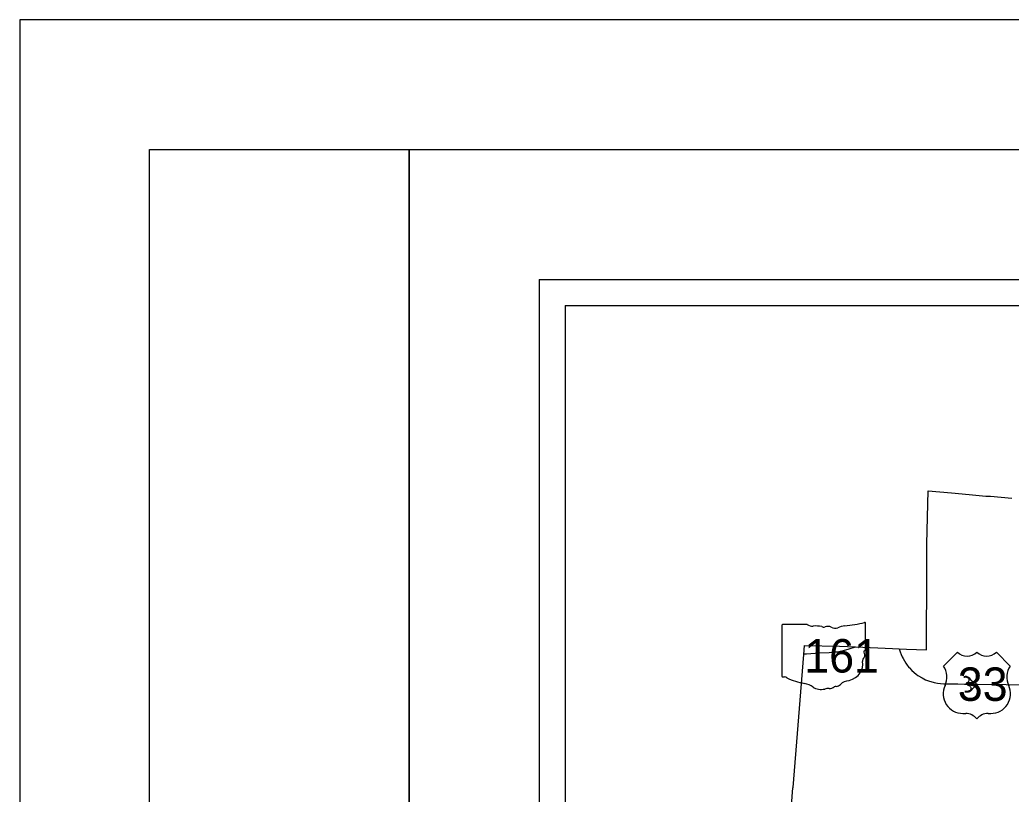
# Model space of a CAD drawing. Extents: x -7.1 to 34, y 0 to 22.
# Drawn here: x 0 to 3.818, y 19.017 to 22 of the extents above; entities that cross this region are included whole.
import ezdxf

# ---------------------------------------------------------------- set-up
doc = ezdxf.new("R2010")
doc.units = 0
for name, color, linetype in [('GM_X_County', 7, 'Continuous'), ('GM_X_Interchange_Ramps', 7, 'Continuous'), ('GM_X_State_Route', 7, 'Continuous'), ('GM_X_State_Shield', 7, 'Continuous'), ('GM_X_US_Route', 7, 'Continuous'), ('GM_X_US_Shield', 7, 'Continuous'), ('SH_Border', 7, 'Continuous'), ('SH_Cut_Line', 7, 'Continuous'), ('SH_Data', 7, 'Continuous')]:
    doc.layers.add(name, color=color, linetype=linetype)

msp = doc.modelspace()

# ---------------------------------------------------------------- linework, layer by layer
at = {"layer": 'GM_X_County'}
msp.add_lwpolyline([(2.9721, 18.9726), (2.9776, 19.0414), (2.9777, 19.0424), (3.0191, 19.5546), (3.0219, 19.5892), (3.1568, 19.5864), (3.2189, 19.5849), (3.3608, 19.5777), (3.3865, 19.5769), (3.4145, 19.5759), (3.4535, 19.5747), (3.4923, 19.5733), (3.4923, 19.5757), (3.4931, 19.8797), (3.4929, 19.981), (3.4977, 20.1851), (3.5882, 20.1772), (3.6564, 20.1717), (3.72, 20.1652), (3.7388, 20.1645), (3.8199, 20.1576)], dxfattribs=at)
at = {"layer": 'GM_X_Interchange_Ramps'}
for points in [[(3.6835, 19.4406), (3.6836, 19.4446), (3.6822, 19.4449), (3.6781, 19.4464), (3.6751, 19.4478), (3.6722, 19.4494), (3.6696, 19.4512), (3.6677, 19.4527), (3.6651, 19.4552), (3.6586, 19.4624), (3.6539, 19.4668), (3.6516, 19.468), (3.6486, 19.4691), (3.6463, 19.4696), (3.6438, 19.4698), (3.6413, 19.4695), (3.6375, 19.4693), (3.6359, 19.4691)], [(3.6359, 19.4673), (3.6376, 19.4675), (3.6408, 19.4683), (3.6437, 19.4685), (3.6459, 19.4682), (3.6479, 19.4675), (3.6498, 19.4664), (3.6511, 19.4653), (3.6525, 19.4638), (3.6535, 19.4621), (3.6544, 19.4601), (3.655, 19.4574), (3.6551, 19.4556), (3.6546, 19.453), (3.6536, 19.4506), (3.6519, 19.4482), (3.6501, 19.4466), (3.6478, 19.4454), (3.6445, 19.4446), (3.6447, 19.4409)], [(3.649, 19.4409), (3.649, 19.4374), (3.6525, 19.4367), (3.6544, 19.436), (3.6563, 19.4352), (3.6583, 19.434), (3.6603, 19.4322), (3.6616, 19.4303), (3.6624, 19.4283), (3.663, 19.426), (3.663, 19.4238), (3.6627, 19.4221), (3.6621, 19.4202), (3.6612, 19.4185), (3.6599, 19.4168), (3.6586, 19.4155), (3.6566, 19.4143), (3.6551, 19.4137), (3.6536, 19.4132), (3.6523, 19.413), (3.6499, 19.4128), (3.6419, 19.4125), (3.6401, 19.4125)], [(3.6401, 19.4111), (3.6423, 19.411), (3.6519, 19.4114), (3.6541, 19.4117), (3.6564, 19.4121), (3.6584, 19.4128), (3.6604, 19.4139), (3.6621, 19.4151), (3.6636, 19.4163), (3.665, 19.4178), (3.6707, 19.4244), (3.673, 19.427), (3.6754, 19.4291), (3.6775, 19.4307), (3.6791, 19.4318), (3.6813, 19.4331), (3.6833, 19.434), (3.686, 19.4351), (3.6889, 19.4359), (3.6875, 19.4405)]]:
    msp.add_lwpolyline(points, dxfattribs=at)
at = {"layer": 'GM_X_State_Route'}
msp.add_lwpolyline([(3.0185, 19.5573), (3.0297, 19.5578), (3.0802, 19.5611), (3.117, 19.5632), (3.141, 19.5648), (3.1496, 19.5658), (3.159, 19.5672), (3.1725, 19.5705), (3.1939, 19.5772), (3.2181, 19.5847), (3.2189, 19.5849)], dxfattribs=at)
at = {"layer": 'GM_X_State_Shield'}
for p, q in [((2.935, 19.6672), (2.935, 19.4716)), ((3.0325, 19.6706), (2.9382, 19.6706)), ((3.2572, 19.5731), (3.2572, 19.6754)), ((3.2571, 19.5731), (3.2572, 19.5731))]:
    msp.add_line(p, q, dxfattribs=at)
for centre, major_axis, start_param, end_param in [((2.9387, 19.6676), (0.00373, 0), 1.712693, 3.28349), ((3.055, 19.6933), (0.0362, 0), 4.042523, 4.731795), ((3.067, 19.5608), (0.1299, 0), 1.404758, 1.657858), ((3.0965, 19.6686), (0.0104, 0), 3.836095, 5.185415), ((3.1118, 19.646), (0.0217, 0), 0.950623, 2.079405), ((3.186, 19.6108), (0.0687, 0), 1.699011, 2.107814), ((3.1424, 19.9372), (0.3416, 0), 4.814394, 5.042369), ((3.2536, 19.6758), (0.00359, 0), 6.141152, 7.989035), ((3.1399, 19.677), (0.0261, 0), 4.081561, 5.145723), ((3.2563, 19.5656), (0.00555, 0), 1.883978, 3.671073), ((3.221, 19.5527), (0.0333, 0), 5.934695, 6.695948), ((3.2533, 19.5727), (0.00384, 0), 5.05454, 6.418171), ((3.1615, 19.5173), (0.0854, 0), 5.101752, 6.440018), ((3.27, 19.5303), (0.0242, 0), 2.387724, 3.262537), ((2.9388, 19.4712), (0.00376, 0), 3.00124, 4.508301), ((2.9393, 19.4912), (0.0287, 0), 4.665946, 4.897461), ((2.9452, 19.4603), (0.0104, 0), 0.519207, 1.627899), ((3.076, 19.6361), (0.2467, 0), 4.195997, 4.488961), ((3.0025, 19.3837), (0.0772, 0), 0.823519, 1.323587), ((3.1383, 19.4527), (0.0276, 0), 4.937069, 5.64225), ((3.1976, 19.4167), (0.0468, 0), 1.647645, 2.488434), ((3.0859, 19.4594), (0.049, 0), 4.026481, 4.996735), ((3.1142, 19.3917), (0.0402, 0), 1.495662, 1.94098), ((3.1178, 19.4447), (0.0261, 0), 4.691044, 5.507374), ((3.1414, 19.4258), (0.00735, 0), 1.147584, 2.315152)]:
    msp.add_ellipse(centre, major_axis=major_axis, ratio=0.8, start_param=start_param, end_param=end_param, dxfattribs=at)
at = {"layer": 'GM_X_US_Route'}
for points in [[(3.3865, 19.5769), (3.3903, 19.5654), (3.3944, 19.555), (3.3982, 19.5463), (3.4017, 19.5391), (3.4121, 19.5215), (3.4175, 19.5138), (3.4211, 19.5089)], [(3.4211, 19.5089), (3.4216, 19.5081), (3.4243, 19.5054)], [(3.4243, 19.5054), (3.4264, 19.5031), (3.4357, 19.4931), (3.4514, 19.4796), (3.4586, 19.474), (3.4753, 19.465), (3.488, 19.4577), (3.4993, 19.4535), (3.5215, 19.4464), (3.5345, 19.4444), (3.5458, 19.4428), (3.5583, 19.4419), (3.5829, 19.4416)], [(3.5829, 19.4416), (3.613, 19.4413), (3.638, 19.4407)], [(3.638, 19.4407), (3.6447, 19.4409), (3.649, 19.4409), (3.6835, 19.4406), (3.6875, 19.4405), (3.7989, 19.4388), (3.8628, 19.4382), (3.8894, 19.4377), (3.8976, 19.4376)]]:
    msp.add_lwpolyline(points, dxfattribs=at)
at = {"layer": 'GM_X_US_Shield'}
for p, q in [((3.6106, 19.5641), (3.5569, 19.5104)), ((3.8146, 19.5104), (3.7609, 19.5641)), ((3.6321, 19.3279), (3.6428, 19.3279)), ((3.7287, 19.3279), (3.7394, 19.3279))]:
    msp.add_line(p, q, dxfattribs=at)
for centre, radius, start, end in [((3.6482, 19.6025), 0.0537, 225.573, 314.427), ((3.7233, 19.6025), 0.0537, 225.573, 314.427), ((3.4953, 19.4673), 0.0752, 334.5471, 35.0009), ((3.8762, 19.4673), 0.0752, 144.9991, 205.4529), ((3.6312, 19.4031), 0.0752, 154.8319, 270.6383), ((3.7403, 19.4031), 0.0752, 269.3617, 25.1681), ((3.6428, 19.2742), 0.0537, 36.8699, 90), ((3.7287, 19.2742), 0.0537, 90, 143.1301)]:
    msp.add_arc(centre, radius, start, end, dxfattribs=at)
at = {"layer": 'SH_Border'}
for points in [[(0.5, 21.5), (1.5, 21.5), (1.5, 0.5), (0.5, 0.5)], [(1.5, 21.5), (33.5, 21.5), (33.5, 0.5), (1.5, 0.5)]]:
    msp.add_lwpolyline(points, close=True, dxfattribs=at)
at = {"layer": 'SH_Cut_Line'}
msp.add_lwpolyline([(0, 0), (34, 0), (34, 22), (0, 22)], close=True, dxfattribs=at)
at = {"layer": 'SH_Data'}
for p, q in [((2, 21), (9, 21)), ((2, 21), (2, 14)), ((2.1, 20.9), (2.1, 14.1)), ((2.1, 20.9), (8.9, 20.9))]:
    msp.add_line(p, q, dxfattribs=at)

# ---------------------------------------------------------------- texts
at = {"layer": 'GM_X_State_Shield'}
msp.add_text('161', height=0.12885, dxfattribs=at).set_placement((3.0212, 19.4854))
at = {"layer": 'GM_X_US_Shield'}
msp.add_text('33', height=0.12885, dxfattribs=at).set_placement((3.6124, 19.3762))

doc.saveas('drawing.dxf')
